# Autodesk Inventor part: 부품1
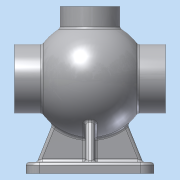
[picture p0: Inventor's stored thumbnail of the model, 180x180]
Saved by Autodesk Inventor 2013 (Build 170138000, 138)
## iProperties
Created: 2018-06
Part Number: 부품1
Material: 알루미늄 6061
Document SubType Name: Modeling
Designer: Administrator
Density: 2.71 g/cm^3
Mass: 1509.58 g
Surface Area: 1153.7 cm^2
Volume: 557.041 cm^3
Author: Administrator
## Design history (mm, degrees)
sketch "스케치1"
  geometry: L1 (68, 0)-(-68, 0); L2 (-68, 0)-(-68, 31); L3 (-68, 31)-(-42.988, 31); L4 (68, 0)-(68, 31); L5 (68, 31)-(42.988, 31); L6 (-68, 17.5)-(-39.278, 17.5); L7 (39.278, 17.5)-(68, 17.5); A1 r 53 centre (0, 0) between (42.988, 31) and (-42.988, 31); A2 r 43 centre (0, 0) between (39.278, 17.5) and (-39.278, 17.5); 2 further points
  constraints: 14 end point, 4 perpendicular, 4 point on circle, 3 coincident, 2 centre point, 2 point on line, 1 horizontal, 1 midpoint, 1 parallel
  dimensions: "d0" = 106 diameter of A1; "d1" = 86 diameter of A2; "d2" = 136 distance of L1.start L1.end; "d3" = 62 diameter of L3 L1; "d4" = 62 diameter of L5 L1; "d6" = 35 diameter of L6 L1; "d7" = 35 diameter of L7 L1
revolve "회전1" sketch "스케치1" stored, may be unused: angle "d11" = 90 deg
node "작업 평면2"
sketch "스케치2"
  geometry: C1 r 27 at (0, 0); 1 further point
  constraints: 1 centre point, 1 coincident
  dimensions: "d13" = 54 diameter of C1
extrude "돌출1" join sketch "스케치2" stored distance "d14" = 10; taper "d15" = 0 deg
sketch "스케치3"
  geometry: C1 r 27 at (0, 0) reference; C2 r 13 at (0, 0)
  constraints: 1 centre point, 1 coincident
  dimensions: "d16" = 26 diameter of C2
extrude "돌출2" cut sketch "스케치3" stored distance "d17" = 10; taper "d18" = 0 deg
node "작업 평면3"
sketch "스케치4"
  geometry: L1 (-57.5, -62.5)-(57.5, -62.5); L2 (57.5, -62.5)-(57.5, 62.5); L3 (57.5, 62.5)-(-57.5, 62.5); L4 (-57.5, 62.5)-(-57.5, -62.5); L5 (-57.5, -62.5)-(57.5, 62.5); L6 (57.5, -62.5)-(-57.5, 62.5); 1 further point
  constraints: 12 end point, 2 midpoint, 2 parallel, 1 horizontal, 1 perpendicular
  dimensions: "d20" = 115 distance of L3.end L2.end; "d21" = 125 distance of L2.end L1.end
extrude "돌출3" join sketch "스케치4" distance "d22" = 10; taper "d23" = 0 deg
sketch "스케치9"
  geometry: C1 r 17.5 at (0, 0) reference; 1 further point
  constraints: 1 vertical alignment
  dimensions: "d54" = 24 distance of C1.centre point (0, 24)
hole "구멍2" sketch "스케치9" at (0, 24) diameter "d55" = 3.242; stored, may be unused: countersink angle "d59" = 90 deg, drill point angle "d61" = 118 deg; dims "d56" = 16, "d57" = 4, "d58" = 2, "d60" = 19
sketch "스케치10"
  geometry: C1 r 31 at (0, 0) reference; 1 further point
  constraints: 1 vertical alignment
  dimensions: "d65" = 22.5 distance of C1.centre point (0, 22.5)
hole "구멍3" sketch "스케치10" at (0, 22.5) diameter "d66" = 3.242; stored, may be unused: countersink angle "d70" = 90 deg, drill point angle "d72" = 118 deg; dims "d67" = 12, "d68" = 4, "d69" = 2, "d71" = 15
sketch "스케치11"
  geometry: C1 r 13 at (0, 0) reference; 1 further point
  constraints: 1 horizontal alignment
  dimensions: "d76" = 20 distance of C1.centre point (20, 0)
hole "구멍4" sketch "스케치11" at (20, 0) diameter "d77" = 3.242; stored, may be unused: countersink angle "d81" = 90 deg, drill point angle "d83" = 118 deg; dims "d78" = 9, "d79" = 4, "d80" = 2, "d82" = 11
fillet "모깎기1" dims "d87" = 12
sketch "스케치12"
  geometry: C1 r 6 at (-45.5, 50.5); C2 r 6 at (45.5, 50.5); A1 r 12 centre (45.5, 50.5) between (57.5, 50.5) and (45.5, 62.5) reference; A2 r 12 centre (-45.5, 50.5) between (-45.5, 62.5) and (-57.5, 50.5) reference; 1 further point
  constraints: 2 centre point, 2 coincident
  dimensions: "d88" = 12 diameter of C1; "d89" = 12 diameter of C2
extrude "돌출6" cut sketch "스케치12" distance "d90" = 3; taper "d91" = 0 deg
sketch "스케치13"
  geometry: L1 (45.5, 62.5)-(-45.5, 62.5) reference; L2 (-4, -52.5)-(4, -52.5); L3 (4, -52.5)-(4, 52.5); L4 (4, 52.5)-(-4, 52.5); L5 (-4, 52.5)-(-4, -52.5); L6 (-4, -52.5)-(4, 52.5); L7 (4, -52.5)-(-4, 52.5); 1 further point
  constraints: 12 end point, 2 midpoint, 2 parallel, 1 horizontal, 1 perpendicular
  dimensions: "d92" = 8 distance of L3.end L4.end; "d94" = 10 distance between parallel lines of L1 L4
extrude "돌출7" join sketch "스케치13" stored distance "d95" = 3; taper "d96" = 0 deg
feature "면 기울기1" dims angle "d97" = 22 deg
sketch "스케치14"
  geometry: L1 (47.5, -75)-(40.87, -58.59); L2 (39.5, -75)-(51.5, -75) reference; L3 (57.5, -75)-(57.5, -85) reference; 1 further point
  constraints: 2 end point, 1 point on line
  dimensions: "d98" = 10 distance from line of L1.start L3; "d99" = 22 deg angle of L1 L3
feature "리브2" sketch "스케치14" dims "d100" = 1, "d101" = 8, "d102" = 0, "d103" = 0, "d104" = 1, "d105" = 1
hole "구멍5" diameter "d108" = 8; stored, may be unused: countersink angle "d112" = 90 deg, drill point angle "d114" = 0 deg; dims "d106" = 10, "d107" = 10, "d109" = 9, "d110" = 4, "d111" = 2, "d113" = 11
node "작업 평면4"
sketch "스케치15"
  geometry: L1 (-27, 0)-(27, 0) reference; 2 further points
  constraints: 1 vertical alignment, 1 other
  dimensions: "d115" = 10 distance from line of L1 point (0, -10)
feature "엠보싱1" sketch "스케치15" dims "d0" = 106, "d1" = 86, "d2" = 136, "d3" = 62, "d4" = 62, "d6" = 35, "d7" = 35, "d116" = 0.5, "d117" = 0
sketch "스케치17"
  geometry: L1 (50.25, 17.5)-(52, 17.5); L2 (52, 17.5)-(52, 18.5); L3 (52, 18.5)-(50.25, 18.5); L4 (50.25, 18.5)-(50.25, 17.5); L5 (68, -31)-(68, 31) reference; L6 (-95.2, 0)-(95.2, 0) reference; 1 further point
  constraints: 8 end point, 2 parallel, 1 horizontal, 1 perpendicular
  dimensions: "d120" = 1.75 distance of L1.start L1.end; "d122" = 18.5 distance from line of L3 point (0, 0); "d123" = 16 distance between parallel lines of L5 L2; "d124" = 17.5 distance from line of L1 point (0, 0)
revolve "회전2" sketch "스케치17" stored, may be unused: angle "d125" = 90 deg
fillet "모깎기2" dims "d126" = 3
fillet "모깎기3" dims "d127" = 3
fillet "모깎기4" dims "d128" = 3
chamfer "모따기1" distance "d129" = 1; stored, may be unused: second distance "d130" = 2, angle "d131" = 45 deg
sketch "스케치20"
  geometry: L1 (-47.5, -75)-(-38.635, -53.058); L2 (-57.5, -78)-(-57.5, -85) reference; L3 (-51.5, -75)-(-39.5, -75) reference; 1 further point
  constraints: 2 end point, 1 point on line
  dimensions: "d133" = 10 distance from line of L2 L1.start; "d134" = 22 deg angle of L2 L1
feature "리브3" sketch "스케치20" dims "d135" = 1, "d136" = 8, "d137" = 0, "d138" = 0, "d139" = 1, "d140" = 1
fillet "모깎기6" dims "d142" = 3
fillet "모깎기7" dims "d143" = 3
node "솔리드1"
pattern_circular "원형 패턴2" dims angle "d63" = 360 deg
pattern_circular "원형 패턴3" dims angle "d74" = 360 deg
pattern_circular "원형 패턴4" dims angle "d85" = 360 deg
mirror "대칭3"
mirror "대칭4"
other parameters: "d12" = 65, "d19" = -85
